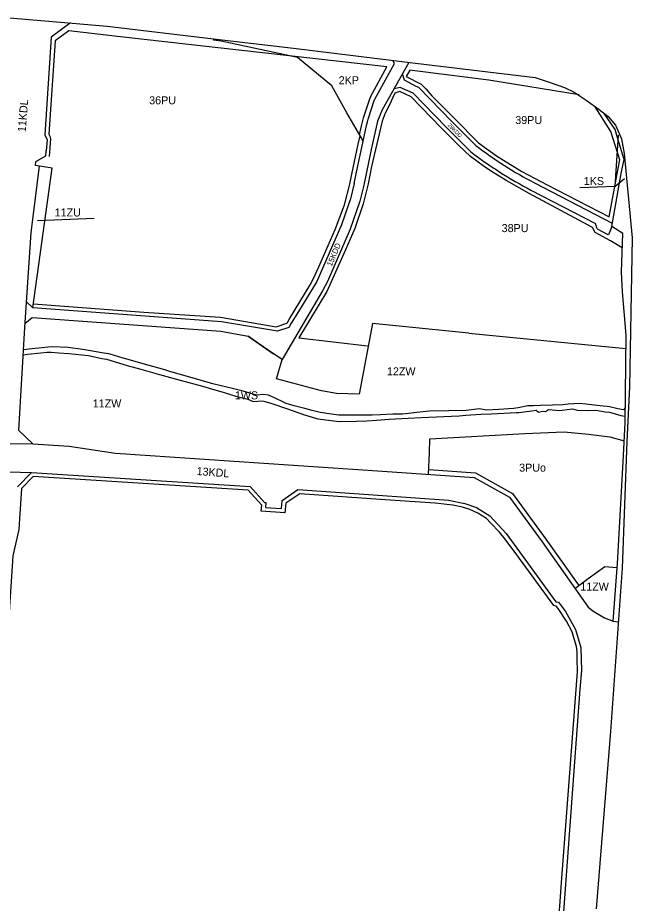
# Model space of a CAD drawing. Extents: x 7428203 to 7432868, y 5542672 to 5545406.
# Drawn here: x 7432101 to 7432868, y 5543958 to 5545064 of the extents above; entities that cross this region are included whole.
import ezdxf

# ---------------------------------------------------------------- set-up
doc = ezdxf.new("R2010")
doc.units = 0
for name, color, linetype in [('granica_planu', 7, 'Continuous'), ('linie_rozgraniczajace', 7, 'Continuous'), ('linie_zabudowy_nieprzekraczalne', 7, 'Continuous'), ('oznaczenia_przeznaczen', 7, 'Continuous')]:
    doc.layers.add(name, color=color, linetype=linetype)

msp = doc.modelspace()

# ---------------------------------------------------------------- linework, layer by layer
at = {"layer": 'granica_planu'}
msp.add_lwpolyline([(7432091.43, 5545063.63), (7432213.18, 5545053.04), (7432345.71, 5545037.18), (7432445.39, 5545025.5), (7432597.63, 5545006.78), (7432746.98, 5544988.98), (7432765.61, 5544982.61), (7432783.5, 5544976.31), (7432795.59, 5544970.56), (7432810.49, 5544960.62), (7432827.01, 5544948.95), (7432837.91, 5544940.2), (7432847.35, 5544929.62), (7432854.48, 5544912.49), (7432858.05, 5544894.08), (7432868.11, 5544788.72), (7432864.81, 5544602.66), (7432861.15, 5544534.46), (7432855.34, 5544376.46), (7432841.11, 5544172.46), (7432823.11, 5543950.75)], dxfattribs=at)
at = {"layer": 'linie_rozgraniczajace'}
for p, q in [((7432091.43, 5545063.63), (7432213.18, 5545053.04)), ((7432167.14, 5545057.04), (7432143.35, 5545039.53)), ((7432213.18, 5545053.04), (7432345.71, 5545037.18)), ((7432143.35, 5545039.53), (7432135.11, 5544917.3)), ((7432345.71, 5545037.18), (7432445.39, 5545025.5)), ((7432445.39, 5545025.5), (7432597.63, 5545006.78)), ((7432597.63, 5545006.78), (7432746.98, 5544988.98)), ((7432583.94, 5544985.59), (7432581.46, 5544993.37)), ((7432746.98, 5544988.98), (7432765.61, 5544982.61)), ((7432765.61, 5544982.61), (7432783.5, 5544976.31)), ((7432783.5, 5544976.31), (7432795.59, 5544970.56)), ((7432795.59, 5544970.56), (7432810.49, 5544960.62)), ((7432810.49, 5544960.62), (7432827.01, 5544948.95)), ((7432827.01, 5544948.95), (7432837.91, 5544940.2)), ((7432837.91, 5544940.2), (7432847.35, 5544929.62)), ((7432847.35, 5544929.62), (7432854.48, 5544912.49)), ((7432135.11, 5544917.3), (7432138.03, 5544911.06)), ((7432138.03, 5544911.06), (7432137.13, 5544897.57)), ((7432854.48, 5544912.49), (7432858.05, 5544894.08)), ((7432858.05, 5544894.08), (7432868.11, 5544788.72)), ((7432120.35, 5544701.27), (7432144.39, 5544875.6)), ((7432144.39, 5544875.6), (7432123.51, 5544878.99)), ((7432741.7, 5544848.46), (7432822.03, 5544806.7)), ((7432746.31, 5544857.33), (7432843.18, 5544806.98)), ((7432824.16, 5544799.96), (7432822.03, 5544806.7)), ((7432824.16, 5544799.96), (7432837.47, 5544793.04)), ((7432868.11, 5544788.72), (7432864.81, 5544602.66)), ((7432111.58, 5544701.91), (7432109.89, 5544676.77)), ((7432442.58, 5544682.22), (7432439.81, 5544676.92)), ((7432544.15, 5544681.61), (7432527.36, 5544593.58)), ((7432664.27, 5544669.74), (7432544.15, 5544681.61)), ((7432109.89, 5544676.77), (7432102.26, 5544548.64)), ((7432401.7, 5544656.62), (7432388.82, 5544666.14)), ((7432664.27, 5544669.74), (7432860.23, 5544650.77)), ((7432420.47, 5544644.07), (7432401.7, 5544656.62)), ((7432431.2, 5544636.91), (7432420.47, 5544644.07)), ((7432424.15, 5544612.61), (7432431.2, 5544636.91)), ((7432480.6, 5544597.68), (7432424.15, 5544612.61)), ((7432499.04, 5544594.43), (7432480.6, 5544597.68)), ((7432527.36, 5544593.58), (7432499.04, 5544594.43)), ((7432864.81, 5544602.66), (7432861.15, 5544534.46)), ((7432102.26, 5544548.64), (7432120.16, 5544531.65)), ((7432036.81, 5544532.49), (7432120.16, 5544531.65)), ((7432120.16, 5544531.65), (7432165.7, 5544528.57)), ((7432165.7, 5544528.57), (7432223.5, 5544519.85)), ((7432861.15, 5544534.46), (7432855.34, 5544376.46)), ((7432223.5, 5544519.85), (7432556.72, 5544497.34)), ((7432052.47, 5544497.76), (7432118.72, 5544495.85)), ((7432118.72, 5544495.85), (7432101.27, 5544477.81)), ((7432556.72, 5544497.34), (7432670.87, 5544489.62)), ((7432670.87, 5544489.62), (7432714.79, 5544465.07)), ((7432714.79, 5544465.07), (7432755.56, 5544409.02)), ((7432755.56, 5544409.02), (7432813.02, 5544327.59)), ((7432855.34, 5544376.46), (7432841.11, 5544172.46)), ((7432844.48, 5544310.25), (7432850.66, 5544309.32)), ((7432841.11, 5544172.46), (7432823.11, 5543950.75))]:
    msp.add_line(p, q, dxfattribs=at)
for points in [[(7432532.33, 5544909.69), (7432512.11, 5544944.8), (7432493.25, 5544978.55), (7432450.29, 5545014.11), (7432355.3, 5545034.46), (7432345.76, 5545035.4), (7432346.32, 5545037.11)], [(7432589.56, 5545007.77), (7432556.27, 5544948.64), (7432550.47, 5544934.35), (7432542.29, 5544899.03), (7432533.1, 5544854.35), (7432528.21, 5544834.46), (7432516.31, 5544799.54), (7432487.72, 5544734.44), (7432481.85, 5544722.68), (7432431.2, 5544636.91)], [(7432521.35, 5544856.8), (7432525.73, 5544878.84), (7432530.56, 5544901.55), (7432536.52, 5544928.9), (7432537.75, 5544933.55), (7432538.63, 5544936.87), (7432546.68, 5544961.65), (7432546.81, 5544962.1), (7432571.38, 5545006.56), (7432569.41, 5545010.25)], [(7432601.97, 5544976.32), (7432598.39, 5544977.94), (7432583.94, 5544985.59)], [(7432594.79, 5544969.36), (7432578.67, 5544976.57), (7432570.92, 5544974.66)], [(7432594.79, 5544969.36), (7432635.53, 5544927.36), (7432666.1, 5544896.72)], [(7432601.97, 5544976.32), (7432642.66, 5544934.37), (7432673.04, 5544904)], [(7432844.48, 5544310.25), (7432849.65, 5544382.15), (7432856.62, 5544508.86), (7432859.31, 5544557.77), (7432860.39, 5544667.1), (7432856.08, 5544721.18), (7432854.52, 5544745.96), (7432856.27, 5544794.18), (7432842.45, 5544802.94), (7432854.26, 5544869.12), (7432856.49, 5544879.21), (7432857.84, 5544886.53), (7432850.24, 5544912.51), (7432846.82, 5544924.02), (7432832.99, 5544944.15)], [(7432123.51, 5544878.99), (7432123.87, 5544884.23), (7432136.71, 5544891.31), (7432137.13, 5544897.57)], [(7432128.19, 5544878.23), (7432117.85, 5544795.62), (7432111.58, 5544701.91)], [(7432521.35, 5544856.8), (7432516.65, 5544837.56), (7432514.2, 5544830.3), (7432505.58, 5544804.83), (7432474.46, 5544734.3), (7432460.89, 5544711.58), (7432451.68, 5544696.86), (7432442.58, 5544682.22)], [(7432842.45, 5544802.94), (7432838.45, 5544792.46), (7432837.47, 5544793.04)], [(7432439.81, 5544676.92), (7432425.59, 5544672.15), (7432355.68, 5544684.07), (7432120.35, 5544701.27), (7432112.07, 5544709.13)], [(7432110.24, 5544681.95), (7432119.48, 5544689.3), (7432354.8, 5544672.11), (7432388.82, 5544666.14), (7432420.47, 5544644.07)], [(7432859.49, 5544575.41), (7432858.62, 5544575.47), (7432857.34, 5544573.97), (7432850.16, 5544575.13), (7432839.66, 5544577.62), (7432836.8, 5544578.15), (7432831.98, 5544578.72), (7432820.48, 5544579.87), (7432810.05, 5544580.91), (7432802.44, 5544582.02), (7432788.1, 5544580.92), (7432781.3, 5544580.39), (7432768.42, 5544579.92), (7432753.63, 5544579.42), (7432744.7, 5544579.11), (7432737.96, 5544578.88), (7432725.57, 5544576.57), (7432720.15, 5544575.5), (7432701.65, 5544574.55), (7432686.23, 5544573.75), (7432677.44, 5544575.28), (7432661.07, 5544572.98), (7432639.27, 5544572.67), (7432615.02, 5544572.15), (7432598.86, 5544570.73), (7432588.97, 5544569.41), (7432581.61, 5544568.51), (7432574.28, 5544568.58), (7432569.41, 5544568.54), (7432554.15, 5544567.82), (7432543.6, 5544567.44), (7432528.27, 5544567.44), (7432517.28, 5544567.39), (7432502.21, 5544567.25), (7432492.71, 5544568.71), (7432478.66, 5544570.84), (7432468.67, 5544573.27), (7432459.82, 5544575.48), (7432446.43, 5544579.14), (7432436.39, 5544581.92), (7432432.94, 5544583.67), (7432422.46, 5544588.5), (7432414.37, 5544592.27), (7432408.79, 5544593.24), (7432399.38, 5544592.46), (7432382.72, 5544597.1), (7432369.38, 5544600.64), (7432355.25, 5544603.92), (7432344.92, 5544606.31), (7432329.11, 5544611.09), (7432313.12, 5544615.73), (7432292.55, 5544621.59), (7432284.9, 5544623.74), (7432257.82, 5544631.37), (7432233.48, 5544638.4), (7432232.89, 5544638.7), (7432216.68, 5544643.47), (7432214.77, 5544643.89), (7432206.49, 5544645.3), (7432185.26, 5544649.01), (7432182.4, 5544649.49), (7432164.36, 5544651.62), (7432144.8, 5544652.86), (7432139.1, 5544652.36), (7432131.98, 5544651.47), (7432123.02, 5544650.58), (7432108.23, 5544648.95)], [(7432107.86, 5544642.78), (7432114.01, 5544643.36), (7432130.14, 5544645.06), (7432138.09, 5544645.89), (7432143.06, 5544645.89), (7432152.83, 5544645.29), (7432165.68, 5544644.52), (7432189.28, 5544641.75), (7432191.93, 5544641.41), (7432206.52, 5544638.27), (7432212.02, 5544637.06), (7432237.93, 5544629.55), (7432255.07, 5544624.68), (7432278.28, 5544618.22), (7432303.92, 5544611.05), (7432331.82, 5544603.39), (7432344.24, 5544599.97), (7432357.88, 5544595.85), (7432373.57, 5544590.94), (7432388.63, 5544587.12), (7432395.01, 5544584.45), (7432406.01, 5544585.14), (7432408.66, 5544584.9), (7432418.38, 5544581.91), (7432436.57, 5544575.64), (7432459.24, 5544567.73), (7432475.89, 5544562.94), (7432502.46, 5544559.23), (7432523.92, 5544559.7), (7432536.91, 5544560.08), (7432548.94, 5544561.22), (7432564.8, 5544562.26), (7432588.61, 5544563.52), (7432604.68, 5544564.57), (7432652.17, 5544566.55), (7432660.28, 5544567.18), (7432672.86, 5544568.29), (7432679.51, 5544568.56), (7432692.47, 5544568.83), (7432723.54, 5544570.59), (7432726.47, 5544570.86), (7432742.64, 5544572.86), (7432748.21, 5544573.48), (7432751.28, 5544571.12), (7432756.21, 5544572.22), (7432760.05, 5544571.83), (7432763.5, 5544574.55), (7432777.23, 5544573.17), (7432793.49, 5544575.37), (7432799.49, 5544573.43), (7432813.31, 5544573.29), (7432822.6, 5544573.57), (7432834.31, 5544571.51), (7432839.75, 5544571.03), (7432853.76, 5544566.93), (7432859.4, 5544566.26)], [(7432613.8, 5544493.48), (7432615.29, 5544520.1), (7432615.7, 5544537.9), (7432733.9, 5544544.47), (7432783.15, 5544546.47), (7432813.62, 5544543.79), (7432839.93, 5544540.39), (7432858.07, 5544535.26)], [(7432118.72, 5544495.85), (7432391.23, 5544478.45), (7432409.46, 5544458.38), (7432411.06, 5544458.22), (7432410.66, 5544451.96), (7432430.56, 5544450.7), (7432431.29, 5544460.59), (7432451.06, 5544474.41), (7432638.86, 5544461.32), (7432659.21, 5544457.07), (7432673.61, 5544451.87), (7432690.23, 5544441.44), (7432710.74, 5544419.65), (7432772.89, 5544334.24), (7432775.94, 5544333.87), (7432784.76, 5544322.31), (7432797.32, 5544299.65), (7432804.1, 5544277.12), (7432804.82, 5544248.59), (7432802.65, 5544225.29), (7432780.32, 5543918.74)], [(7432796.51, 5544351), (7432813.05, 5544363.26), (7432833.76, 5544378.32), (7432848.69, 5544377.18), (7432849.29, 5544377.13)], [(7432813.02, 5544327.59), (7432820.26, 5544322.24), (7432833.57, 5544314.45), (7432844.48, 5544310.25)]]:
    msp.add_lwpolyline(points, dxfattribs=at)
for centre, radius, start, end in [((7432975.2791, 5545297.6527), 496.2972, 232.4836224, 242.5254313), ((7432975.0059, 5545297.2814), 505.8382, 232.3612215, 242.5337305)]:
    msp.add_arc(centre, radius, start, end, dxfattribs=at)
at = {"layer": 'linie_zabudowy_nieprzekraczalne'}
for p, q in [((7432530.72, 5544930.44), (7432532.83, 5544938.41)), ((7432527.88, 5544917.42), (7432530.66, 5544930.18)), ((7432530.66, 5544930.18), (7432530.72, 5544930.44)), ((7432452.02, 5544663.97), (7432537.8, 5544653.76)), ((7432614.13, 5544499.47), (7432672.62, 5544495.52)), ((7432672.62, 5544495.52), (7432718.87, 5544469.67)), ((7432718.87, 5544469.67), (7432760.42, 5544412.55)), ((7432760.47, 5544412.48), (7432801.33, 5544354.57))]:
    msp.add_line(p, q, dxfattribs=at)
for points in [[(7432165.41, 5545047.19), (7432148.04, 5545034.83), (7432140.18, 5544918.25), (7432141.4, 5544915.65), (7432142.39, 5544912.28), (7432140.5, 5544890.37)], [(7432562.12, 5545002.2), (7432225.99, 5545040.31), (7432165.41, 5545047.19)], [(7432541.56, 5544965), (7432562.12, 5545002.2)], [(7432590.44, 5544998.3), (7432585.86, 5544990.22)], [(7432801.98, 5544967.23), (7432689.18, 5544985.8), (7432590.08, 5544998.32)], [(7432585.86, 5544990.22), (7432604.91, 5544980.53), (7432610.43, 5544974.97), (7432618.13, 5544966.23), (7432646.18, 5544937.8), (7432676.2, 5544907.4), (7432698.88, 5544891.23), (7432730.29, 5544871.75), (7432762.14, 5544854.86), (7432839.1, 5544814.78)], [(7432855.58, 5544776.1), (7432840.99, 5544785.13), (7432821.86, 5544795.53), (7432818.33, 5544801.83), (7432739.4, 5544844.02), (7432711.68, 5544859.75), (7432692.52, 5544871.66), (7432682.26, 5544878.68), (7432666.1, 5544890.46), (7432651.57, 5544903.93), (7432629.65, 5544926.25), (7432592.26, 5544964.76), (7432578.2, 5544971.31), (7432571.97, 5544969.24), (7432564.87, 5544953.85)], [(7432532.92, 5544938.73), (7432540.95, 5544963.42), (7432541.05, 5544963.77)], [(7432564.85, 5544953.83), (7432559.94, 5544944.4), (7432555.9, 5544934.44), (7432542.91, 5544877.91), (7432538.54, 5544856.1), (7432532.4, 5544831.27), (7432521.95, 5544800.58), (7432510.52, 5544773.92), (7432487.05, 5544721.9), (7432452.02, 5544663.97)], [(7432839.1, 5544814.78), (7432850.47, 5544875.15), (7432852.7, 5544886.27), (7432841.54, 5544921.64), (7432821.92, 5544952.54)], [(7432516.26, 5544857.94), (7432516.61, 5544860.03), (7432518.4, 5544868.28), (7432526.31, 5544905.89), (7432528.5, 5544916.33)], [(7432497.66, 5544799.34), (7432509.26, 5544829.81), (7432516.09, 5544857.24)], [(7432437.7, 5544682.23), (7432440.52, 5544687.66), (7432466.44, 5544730.19), (7432470.15, 5544737.14), (7432477.17, 5544752.69), (7432497.66, 5544799.34), (7432497.66, 5544799.34)], [(7432121.04, 5544706.22), (7432258.79, 5544696.1), (7432354.49, 5544689.88), (7432423.96, 5544677.5), (7432437.05, 5544682.01)], [(7432388.79, 5544473.79), (7432120.65, 5544490.65), (7432106.14, 5544475.66), (7432103.72, 5544437.8), (7432102.87, 5544424.52), (7432095.51, 5544391.55), (7432087.54, 5544270.16), (7432075.05, 5544080.02), (7432070.49, 5544020.98), (7432069, 5544001.68), (7432073.61, 5543998.74), (7432071.81, 5543971.05)], [(7432774.97, 5543914.1), (7432780.43, 5543989.03), (7432799.63, 5544246.81), (7432799.45, 5544263.31), (7432799.22, 5544272.14), (7432798.53, 5544278.27), (7432795.6, 5544288.02), (7432793.01, 5544296.64), (7432785.92, 5544309.91), (7432775.8, 5544325.82), (7432773.37, 5544329), (7432770.13, 5544329.53), (7432724, 5544392.92), (7432709.66, 5544412.64), (7432702.54, 5544421.07), (7432691.42, 5544432.88), (7432686.16, 5544438.09), (7432675.51, 5544444.78), (7432665.65, 5544449.43), (7432656.13, 5544452.61), (7432644.44, 5544455.05), (7432622.37, 5544457.41), (7432559.89, 5544461.55), (7432453.5, 5544469.22), (7432436.08, 5544457.62), (7432434.71, 5544445.43), (7432405.36, 5544447.28), (7432405.83, 5544454.94), (7432388.89, 5544473.59)]]:
    msp.add_lwpolyline(points, dxfattribs=at)
for centre, radius, start, end in [((7432546.6641, 5544962.1629), 5.8396, 150.9329338, 164.025935), ((7432530.115, 5544939.3463), 2.8719, 340.973581, 347.6091433)]:
    msp.add_arc(centre, radius, start, end, dxfattribs=at)
at = {"layer": 'oznaczenia_przeznaczen'}
for p, q in [((7432846.9, 5544853.38), (7432850.91, 5544916.76)), ((7432197.01, 5544812.99), (7432125.96, 5544810.11))]:
    msp.add_line(p, q, dxfattribs=at)
msp.add_lwpolyline([(7432802.54, 5544851.58), (7432846.9, 5544853.38), (7432858.37, 5544862.73)], dxfattribs=at)

# ---------------------------------------------------------------- texts
for s, p in [('2KP', (7432501.8742, 5544980.58)), ('36PU', (7432265.4728, 5544955.48)), ('39PU', (7432722.1728, 5544930.9)), ('1KS', (7432807.6105, 5544854.72)), ('11ZU', (7432147.5428, 5544815.44)), ('38PU', (7432705.1728, 5544795.92)), ('12ZW', (7432562.0633, 5544617.07)), ('1WS', (7432372.3359, 5544587.08)), ('11ZW', (7432195.0333, 5544576.92)), ('3PUo', (7432726.9877, 5544496.81)), ('11ZW', (7432803.2133, 5544348.25))]:
    msp.add_text(s, height=10, dxfattribs=at).set_placement(p)
for s, height, rotation, p in [('11KDL', 10, 85.5100198, (7432111.3634, 5544920.5025)), ('29KDD', 4.9, 314.7935026, (7432637.4014, 5544929.0381)), ('15KDD', 7, 67.2904119, (7432493.2075, 5544752.6094)), ('13KDL', 10, 355.5331323, (7432324.3137, 5544492.7064))]:
    msp.add_text(s, height=height, rotation=rotation, dxfattribs=at).set_placement(p)

doc.saveas('drawing.dxf')
